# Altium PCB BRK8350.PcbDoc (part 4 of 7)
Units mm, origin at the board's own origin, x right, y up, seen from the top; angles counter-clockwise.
Board outline 240 x 150 mm, 8 copper layers (L1-TOP, L2-GND, L3-PWR, L4-SIG, L5-SIG, L6-PWR, L7-GND, L8-BOT), stack 1.465 mm thick; 277 components, 542 nets, 1814 pads, 2338 vias.
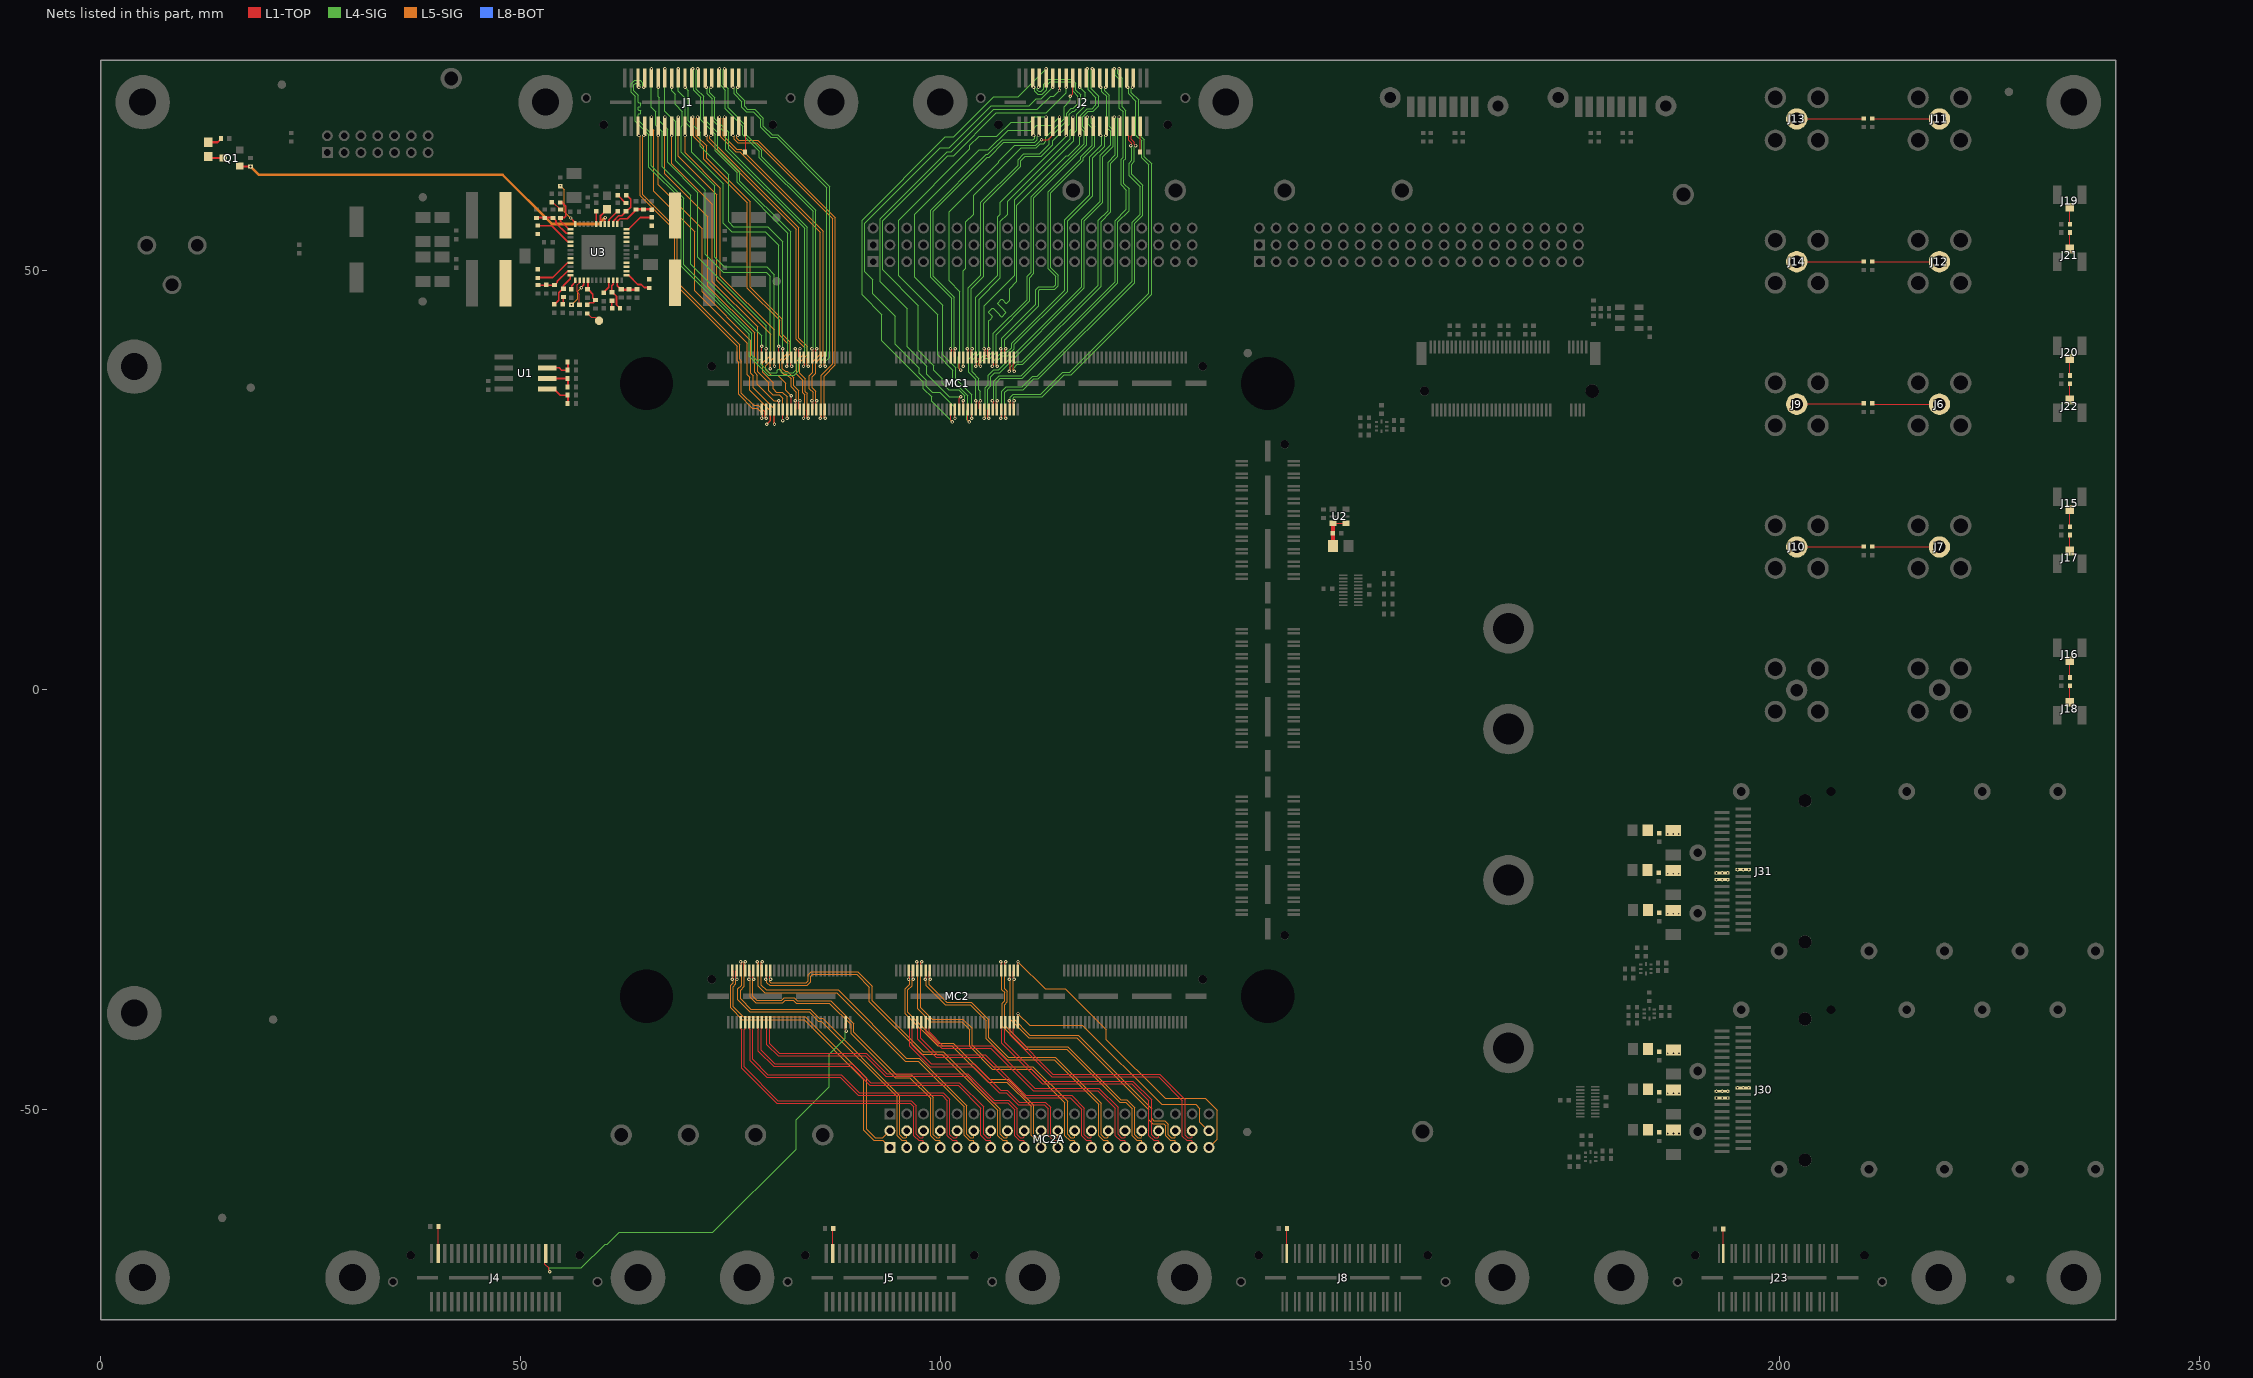
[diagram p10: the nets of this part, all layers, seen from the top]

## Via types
v1: diameter 0.406, hole 0.203, L1-TOP to L8-BOT, tented both sides, 2338 vias

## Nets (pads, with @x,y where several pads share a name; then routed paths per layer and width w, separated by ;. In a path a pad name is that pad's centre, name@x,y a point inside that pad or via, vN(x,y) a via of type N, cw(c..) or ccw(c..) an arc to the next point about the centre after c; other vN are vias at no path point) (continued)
MC2A_1: MC2.3 MC2A.1 | length 34.2
  L1-TOP w0.107: v1(75.212,-34.451) 75.34,-34.323 75.34,-33.5 MC2.3@75.25,-33.41
  L5-SIG w0.107: v1(75.212,-34.451) 75.34,-34.579 75.34,-34.87 75.016,-35.194 75.016,-37.877 76.408,-39.268 83.769,-39.268 90.907,-46.406 90.907,-52.473 92.093,-53.66 93.16,-53.66 MC2A.1@94,-54.5
MC2A_2: MC2.5 MC2A.2 | length 33.6
  L1-TOP w0.107: MC2.5@75.75,-33.41 75.66,-33.5 75.66,-34.323 v1(75.788,-34.451)
  L5-SIG w0.107: v1(75.788,-34.451) 75.66,-34.579 75.66,-35.003 75.336,-35.327 75.336,-37.744 76.54,-38.948 83.902,-38.948 91.227,-46.273 91.227,-52.341 92.226,-53.34 93.16,-53.34 MC2A.2@94,-52.5
MC2A_3: MC2.7 MC2A.3 | length 36.5
  L1-TOP w0.107: v1(76.212,-32.368) 76.34,-32.496 76.34,-33.32 MC2.7@76.25,-33.41
  L5-SIG w0.107: v1(76.212,-32.368) 76.34,-32.496 76.34,-35.166 75.895,-35.611 75.895,-36.928 77.322,-38.354 84.397,-38.354 85.479,-39.436 85.842,-39.436 94.846,-48.44 94.846,-53.085 95.421,-53.66 95.916,-53.66 96,-53.745 MC2A.3@96,-54.5
MC2A_4: MC2.9 MC2A.4 | length 35.9
  L1-TOP w0.107: MC2.9@76.75,-33.41 76.66,-33.32 76.66,-32.496 v1(76.789,-32.368)
  L5-SIG w0.107: v1(76.789,-32.368) 76.66,-32.496 76.66,-35.298 76.215,-35.743 76.215,-36.795 77.454,-38.034 84.529,-38.034 85.611,-39.116 85.974,-39.116 95.166,-48.308 95.166,-52.953 95.553,-53.34 95.916,-53.34 96,-53.255 MC2A.4@96,-52.5
MC2A_5: MC2.8 MC2A.5 | length 33.5
  L1-TOP w0.107: MC2.8@76.25,-39.59 76.25,-40.368 76.34,-40.458 76.34,-45.043 80.537,-49.24 96.419,-49.24 96.842,-49.663 96.842,-53.075 97.427,-53.66 97.922,-53.66 98,-53.738 MC2A.5@98,-54.5
MC2A_6: MC2.10 MC2A.6 | length 33
  L1-TOP w0.107: MC2.10@76.75,-39.59 76.75,-40.368 76.66,-40.458 76.66,-44.91 80.67,-48.92 96.552,-48.92 97.162,-49.531 97.162,-52.942 97.56,-53.34 97.922,-53.34 98,-53.262 MC2A.6@98,-52.5
MC2A_7: MC2.11 MC2A.7 | length 37.3
  L1-TOP w0.107: v1(77.212,-34.451) 77.34,-34.323 77.34,-33.5 MC2.11@77.25,-33.41
  L5-SIG w0.107: v1(77.212,-34.451) 77.34,-34.579 77.34,-36.62 78.008,-37.287 81.225,-37.287 81.555,-36.957 82.474,-36.957 82.834,-37.318 86.797,-37.318 89.383,-39.903 89.383,-40.933 94.616,-46.167 96.381,-46.167 98.847,-48.632 98.847,-53.085 99.421,-53.66 99.903,-53.66 100,-53.757 MC2A.7@100,-54.5
MC2A_8: MC2.13 MC2A.8 | length 36.8
  L1-TOP w0.107: MC2.13@77.75,-33.41 77.66,-33.5 77.66,-34.323 v1(77.788,-34.451)
  L5-SIG w0.107: v1(77.788,-34.451) 77.66,-34.579 77.66,-36.487 78.141,-36.967 81.092,-36.967 81.422,-36.637 82.606,-36.637 82.967,-36.998 86.929,-36.998 89.703,-39.771 89.703,-40.801 94.749,-45.847 96.514,-45.847 99.167,-48.5 99.167,-52.953 99.554,-53.34 99.903,-53.34 100,-53.243 MC2A.8@100,-52.5
MC2A_9: MC2.12 MC2A.9 | length 36.4
  L1-TOP w0.107: MC2.12@77.25,-39.59 77.25,-40.368 77.34,-40.458 77.34,-44.142 79.34,-46.142 88.067,-46.142 90.2,-48.275 100.204,-48.275 100.836,-48.907 100.836,-53.085 101.411,-53.66 101.897,-53.66 102,-53.763 MC2A.9@102,-54.5
MC2A_10: MC2.14 MC2A.10 | length 35.9
  L1-TOP w0.107: MC2.14@77.75,-39.59 77.75,-40.368 77.66,-40.458 77.66,-44.009 79.473,-45.822 88.199,-45.822 90.333,-47.955 100.337,-47.955 101.156,-48.774 101.156,-52.952 101.544,-53.34 101.897,-53.34 102,-53.237 MC2A.10@102,-52.5
MC2A_11: MC2.15 MC2A.11 | length 40.1
  L1-TOP w0.107: v1(78.212,-32.368) 78.34,-32.496 78.34,-33.32 MC2.15@78.25,-33.41
  L5-SIG w0.107: v1(78.212,-32.368) 78.34,-32.496 78.34,-35.283 79.115,-36.058 87.694,-36.058 95.839,-44.202 97.382,-44.202 102.834,-49.655 102.834,-53.035 103.46,-53.66 103.917,-53.66 104,-53.744 MC2A.11@104,-54.5
MC2A_12: MC2.17 MC2A.12 | length 39.6
  L1-TOP w0.107: MC2.17@78.75,-33.41 78.66,-33.32 78.66,-32.496 v1(78.788,-32.368)
  L5-SIG w0.107: v1(78.788,-32.368) 78.66,-32.496 78.66,-35.15 79.248,-35.738 87.827,-35.738 95.971,-43.882 97.515,-43.882 103.155,-49.522 103.155,-52.902 103.592,-53.34 103.917,-53.34 104,-53.256 MC2A.12@104,-52.5
MC2A_13: MC2.16 MC2A.13 | length 38.2
  L1-TOP w0.107: MC2.16@78.25,-39.59 78.25,-40.368 78.34,-40.458 78.34,-43.03 80.157,-44.846 89.377,-44.846 91.612,-47.081 102.128,-47.081 104.841,-49.795 104.841,-53.059 105.443,-53.66 105.91,-53.66 106,-53.75 MC2A.13@106,-54.5
MC2A_14: MC2.18 MC2A.14 | length 37.7
  L1-TOP w0.107: MC2.18@78.75,-39.59 78.75,-40.368 78.66,-40.458 78.66,-42.897 80.289,-44.526 89.51,-44.526 91.745,-46.761 102.26,-46.761 105.161,-49.662 105.161,-52.926 105.575,-53.34 105.91,-53.34 106,-53.25 MC2A.14@106,-52.5
MC2A_15: MC2.19 MC2A.15 | length 43.1
  L1-TOP w0.107: v1(79.212,-34.451) 79.34,-34.323 79.34,-33.5 MC2.19@79.25,-33.41
  L5-SIG w0.107: v1(79.212,-34.451) 79.34,-34.579 79.34,-34.865 79.68,-35.204 84.146,-35.204 84.597,-34.753 84.597,-34.08 84.793,-33.884 90.043,-33.884 91.567,-35.408 91.567,-37.13 97.854,-43.418 100.191,-43.418 106.835,-50.061 106.835,-53.073 107.422,-53.66 107.917,-53.66 108,-53.743 MC2A.15@108,-54.5
MC2A_16: MC2.21 MC2A.16 | length 42.6
  L1-TOP w0.107: MC2.21@79.75,-33.41 79.66,-33.5 79.66,-34.323 v1(79.788,-34.451)
  L5-SIG w0.107: v1(79.788,-34.451) 79.66,-34.579 79.66,-34.732 79.812,-34.884 84.013,-34.884 84.277,-34.62 84.277,-33.947 84.661,-33.564 90.176,-33.564 91.887,-35.275 91.887,-36.998 97.987,-43.098 100.324,-43.098 107.155,-49.929 107.155,-52.94 107.555,-53.34 107.917,-53.34 108,-53.257 MC2A.16@108,-52.5
MC2A_17: MC2.20 MC2A.17 | length 40.7
  L1-TOP w0.107: MC2.20@79.25,-39.59 79.25,-40.368 79.34,-40.458 79.34,-42.252 80.68,-43.591 91.054,-43.591 93.478,-46.015 103.144,-46.015 106.319,-49.19 108.031,-49.19 108.842,-50 108.842,-53.097 109.405,-53.66 109.898,-53.66 110,-53.762 MC2A.17@110,-54.5
MC2A_18: MC2.22 MC2A.18 | length 40.1
  L1-TOP w0.107: MC2.22@79.75,-39.59 79.75,-40.368 79.66,-40.458 79.66,-42.119 80.812,-43.271 91.187,-43.271 93.61,-45.695 103.276,-45.695 106.451,-48.87 108.164,-48.87 109.162,-49.868 109.162,-52.964 109.537,-53.34 109.898,-53.34 110,-53.238 MC2A.18@110,-52.5
MC2A_19: MC2.67 MC2A.19 | length 30.7
  L1-TOP w0.107: v1(96.212,-34.451) 96.34,-34.323 96.34,-33.5 MC2.67@96.25,-33.41
  L5-SIG w0.107: v1(96.212,-34.451) 96.34,-34.579 96.34,-35.077 95.834,-35.584 95.834,-38.548 99.686,-42.399 101.382,-42.399 105.7,-46.717 107.942,-46.717 110.835,-49.61 110.835,-53.068 111.427,-53.66 111.892,-53.66 112,-53.768 MC2A.19@112,-54.5
MC2A_20: MC2.69 MC2A.20 | length 30.2
  L1-TOP w0.107: MC2.69@96.75,-33.41 96.66,-33.5 96.66,-34.323 v1(96.788,-34.451)
  L5-SIG w0.107: v1(96.788,-34.451) 96.66,-34.579 96.66,-35.21 96.154,-35.716 96.154,-38.415 99.818,-42.079 101.515,-42.079 105.833,-46.397 108.075,-46.397 111.156,-49.478 111.156,-52.936 111.56,-53.34 111.892,-53.34 112,-53.232 MC2A.20@112,-52.5
MC2A_21: MC2.68 MC2A.21 | length 27.8
  L1-TOP w0.107: MC2.68@96.25,-39.59 96.25,-40.094 96.34,-40.184 96.34,-42.436 98.776,-44.872 103.901,-44.872 107.016,-47.986 107.853,-47.986 109.278,-49.412 112.39,-49.412 112.842,-49.864 112.842,-53.028 113.474,-53.66 113.911,-53.66 114,-53.749 MC2A.21@114,-54.5
MC2A_22: MC2.70 MC2A.22 | length 27.3
  L1-TOP w0.107: MC2.70@96.75,-39.59 96.75,-39.973 96.66,-40.063 96.66,-42.304 98.908,-44.552 104.059,-44.552 107.174,-47.666 107.985,-47.666 109.411,-49.092 112.523,-49.092 113.162,-49.732 113.162,-52.895 113.607,-53.34 113.911,-53.34 114,-53.251 MC2A.22@114,-52.5
MC2A_23: MC2.71 MC2A.23 | length 36.2
  L1-TOP w0.107: v1(97.212,-32.368) 97.34,-32.496 97.34,-33.32 MC2.71@97.25,-33.41
  L5-SIG w0.107: v1(97.212,-32.368) 97.34,-32.496 97.34,-37.976 98.887,-39.522 102.565,-39.522 103.49,-40.447 103.49,-42.463 106.201,-45.174 110.87,-45.174 114.836,-49.14 114.836,-53.073 115.423,-53.66 115.918,-53.66 116,-53.742 MC2A.23@116,-54.5
MC2A_24: MC2.73 MC2A.24 | length 35.7
  L1-TOP w0.107: MC2.73@97.75,-33.41 97.66,-33.32 97.66,-32.496 v1(97.788,-32.368)
  L5-SIG w0.107: v1(97.788,-32.368) 97.66,-32.496 97.66,-37.843 99.019,-39.202 102.698,-39.202 103.81,-40.314 103.81,-42.33 106.333,-44.854 111.002,-44.854 115.156,-49.008 115.156,-52.94 115.556,-53.34 115.918,-53.34 116,-53.258 MC2A.24@116,-52.5
MC2A_25: MC2.72 MC2A.25 | length 30.3
  L1-TOP w0.107: MC2.72@97.25,-39.59 97.25,-40.159 97.34,-40.249 97.34,-41.602 98.877,-43.138 99.492,-43.754 105.197,-43.754 110.042,-48.599 115.502,-48.599 116.843,-49.94 116.843,-53.089 117.414,-53.66 117.925,-53.66 118,-53.735 MC2A.25@118,-54.5
MC2A_26: MC2.74 MC2A.26 | length 29.8
  L1-TOP w0.107: MC2.74@97.75,-39.59 97.75,-40.132 97.66,-40.222 97.66,-41.469 99.625,-43.434 105.329,-43.434 110.174,-48.279 115.635,-48.279 117.163,-49.807 117.163,-52.956 117.546,-53.34 117.925,-53.34 118,-53.265 MC2A.26@118,-52.5
MC2A_27: MC2.75 MC2A.27 | length 35.5
  L1-TOP w0.107: v1(98.212,-34.451) 98.34,-34.323 98.34,-33.5 MC2.75@98.25,-33.41
  L5-SIG w0.107: v1(98.212,-34.451) 98.34,-34.579 98.34,-35.242 100.608,-37.51 103.546,-37.51 105.461,-39.425 105.461,-41.568 107.961,-44.069 113.568,-44.069 118.849,-49.35 118.849,-53.085 119.424,-53.66 119.906,-53.66 120,-53.754 MC2A.27@120,-54.5
MC2A_28: MC2.77 MC2A.28 | length 35
  L1-TOP w0.107: MC2.77@98.75,-33.41 98.66,-33.5 98.66,-34.323 v1(98.788,-34.451)
  L5-SIG w0.107: v1(98.788,-34.451) 98.66,-34.579 98.66,-35.11 100.74,-37.19 103.678,-37.19 105.781,-39.292 105.781,-41.436 108.094,-43.749 113.701,-43.749 119.169,-49.218 119.169,-52.953 119.556,-53.34 119.906,-53.34 120,-53.246 MC2A.28@120,-52.5
MC2A_29: MC2.76 MC2A.29 | length 32.9
  L1-TOP w0.107: MC2.76@98.25,-39.59 98.25,-40.059 98.34,-40.149 98.34,-40.856 100.172,-42.687 106.035,-42.687 111.093,-47.746 118.75,-47.746 120.846,-49.841 120.846,-53.075 121.43,-53.66 121.912,-53.66 122,-53.748 MC2A.29@122,-54.5
MC2A_30: MC2.78 MC2A.30 | length 32.4
  L1-TOP w0.107: MC2.78@98.75,-39.59 98.75,-39.982 98.66,-40.072 98.66,-40.723 100.305,-42.367 106.167,-42.367 111.226,-47.426 118.883,-47.426 121.166,-49.709 121.166,-52.943 121.563,-53.34 121.912,-53.34 122,-53.252 MC2A.30@122,-52.5
MC2A_31: MC2.111 MC2A.31 | length 34.1
  L1-TOP w0.107: v1(107.212,-32.368) 107.34,-32.496 107.34,-33.32 MC2.111@107.25,-33.41
  L5-SIG w0.107: v1(107.212,-32.368) 107.34,-32.496 107.34,-35.708 107.671,-36.038 107.671,-37.02 107.353,-37.338 107.353,-40.064 110.114,-42.824 115.062,-42.824 121.351,-49.113 122.067,-49.113 122.84,-49.886 122.84,-53.101 123.399,-53.66 123.906,-53.66 124,-53.754 MC2A.31@124,-54.5
MC2A_32: MC2.113 MC2A.32 | length 33.6
  L1-TOP w0.107: MC2.113@107.75,-33.41 107.66,-33.32 107.66,-32.496 v1(107.788,-32.368)
  L5-SIG w0.107: v1(107.788,-32.368) 107.66,-32.496 107.66,-35.575 107.991,-35.905 107.991,-37.153 107.673,-37.471 107.673,-39.931 110.246,-42.504 115.195,-42.504 121.484,-48.793 122.2,-48.793 123.16,-49.753 123.16,-52.968 123.531,-53.34 123.906,-53.34 124,-53.246 MC2A.32@124,-52.5
MC2A_33: MC2.112 MC2A.33 | length 29.2
  L1-TOP w0.107: MC2.112@107.25,-39.59 107.25,-40.368 107.34,-40.458 107.34,-42.088 112.16,-46.908 122.809,-46.908 124.844,-48.943 124.844,-53.085 125.418,-53.66 125.9,-53.66 126,-53.76 MC2A.33@126,-54.5
MC2A_34: MC2.114 MC2A.34 | length 28.7
  L1-TOP w0.107: MC2.114@107.75,-39.59 107.75,-40.368 107.66,-40.458 107.66,-41.955 112.293,-46.588 122.941,-46.588 125.164,-48.81 125.164,-52.953 125.551,-53.34 125.9,-53.34 126,-53.24 MC2A.34@126,-52.5
MC2A_35: MC2.115 MC2A.35 | length 33.8
  L1-TOP w0.107: v1(108.212,-34.451) 108.34,-34.323 108.34,-33.5 MC2.115@108.25,-33.41
  L5-SIG w0.107: v1(108.212,-34.451) 108.34,-34.579 108.34,-39.222 110.545,-41.427 116.281,-41.427 124.841,-49.987 124.841,-51.176 125.318,-51.653 126.601,-51.653 126.84,-51.892 126.84,-53.113 127.387,-53.66 127.932,-53.66 128,-53.728 MC2A.35@128,-54.5
MC2A_36: MC2.117 MC2A.36 | length 33.3
  L1-TOP w0.107: MC2.117@108.75,-33.41 108.66,-33.5 108.66,-34.323 v1(108.788,-34.451)
  L5-SIG w0.107: v1(108.788,-34.451) 108.66,-34.579 108.66,-39.09 110.678,-41.107 116.414,-41.107 125.161,-49.855 125.161,-51.044 125.451,-51.333 126.734,-51.333 127.16,-51.76 127.16,-52.981 127.519,-53.34 127.932,-53.34 128,-53.272 MC2A.36@128,-52.5
MC2A_37: MC2.116 MC2A.37 | length 31.7
  L1-TOP w0.107: MC2.116@108.25,-39.59 108.25,-40.368 108.34,-40.458 108.34,-41.157 113.278,-46.095 126.015,-46.095 128.847,-48.927 128.847,-53.164 129.343,-53.66 129.913,-53.66 130,-53.747 MC2A.37@130,-54.5
MC2A_38: MC2.118 MC2A.38 | length 31.2
  L1-TOP w0.107: MC2.118@108.75,-39.59 108.75,-40.368 108.66,-40.458 108.66,-41.025 113.41,-45.775 126.147,-45.775 129.167,-48.794 129.167,-53.032 129.475,-53.34 129.913,-53.34 130,-53.253 MC2A.38@130,-52.5
MC2A_39: MC2.119 MC2A.39 | length 37.6
  L1-TOP w0.114: MC2.119@109.25,-33.41 v1(109.25,-32.37)
  L5-SIG w0.117: v1(109.25,-32.37) 112.494,-35.614 114.912,-35.614 119.786,-40.488 119.786,-41.656 126.771,-48.641 131.547,-48.641 132.994,-50.089 132.994,-53.506 MC2A.39@132,-54.5
MC2A_40: MC2.120 MC2A.40 | length 30.5
  L1-TOP w0.114: MC2.120@109.25,-39.59 v1(109.25,-38.55)
  L5-SIG w0.117: v1(109.25,-38.55) 110.629,-39.929 116.916,-39.929 126.365,-49.378 130.404,-49.378 130.912,-49.886 130.912,-51.511 MC2A.40@131.953,-52.553
NetC4_2: C4.2 FB7.2 U2.1 U2.6 | length 4.2
  L1-TOP w0.127: U2.6@146.779,19.844 U2.1@148.329,19.844
  L1-TOP w0.508: U2.6@146.779,19.844 146.779,17.166 FB7.2@146.793,17.151
NetC6_1: C6.1 J6.1 | length 8
  L1-TOP w0.107: C6.1@210.99,34.07 ccw(c211.097,34.177) 211.097,34.026 J6.1@219,34.026
NetC7_1: C7.1 J7.1 | length 8
  L1-TOP w0.107: C7.1@210.99,17.027 J7.1@219,17.026
NetC8_1: C8.1 J9.1 | length 8
  L1-TOP w0.107: J9.1@202,34.026 cw(c202.107,33.919) 202.107,34.07 C8.1@210,34.07
NetC9_1: C9.1 J10.1 | length 8
  L1-TOP w0.107: J10.1@202,17.026 C9.1@209.999,17.026
NetC10_1: C10.1 J11.1 | length 7.9
  L1-TOP w0.107: C10.1@211.102,68.005 211.108,68.005 211.113,68 J11.1@219,68
NetC11_1: C11.1 J12.1 | length 8
  L1-TOP w0.107: C11.1@210.99,50.977 218.945,50.977 ccw(c218.945,51.055) J12.1@219,51
NetC12_1: C12.1 J13.1 | length 7.9
  L1-TOP w0.107: J13.1@202,68 209.887,68 209.892,68.005 C12.1@209.898,68.005
NetC13_1: C13.1 J14.1 | length 8
  L1-TOP w0.107: J14.1@202,51 209.945,51 cw(c209.945,50.923) C13.1@210,50.977
NetC14_1: C14.1 J15.1 | length 2
  L1-TOP w0.107: C14.1@234.493,19.449 234.5,19.456 J15.1@234.5,21.475
NetC15_1: C15.1 J16.1 | length 2
  L1-TOP w0.107: C15.1@234.493,1.475 234.5,1.481 J16.1@234.5,3.475
NetC16_1: C16.1 J17.1 | length 1.9
  L1-TOP w0.107: C16.1@234.493,18.449 234.5,18.443 J17.1@234.5,16.525
NetC17_1: C17.1 J18.1 | length 2
  L1-TOP w0.107: C17.1@234.493,0.475 234.5,0.468 J18.1@234.5,-1.475
NetC18_1: C18.1 J19.1 | length 2
  L1-TOP w0.107: C18.1@234.493,55.475 234.5,55.481 J19.1@234.5,57.475
NetC19_1: C19.1 J20.1 | length 2
  L1-TOP w0.107: C19.1@234.493,37.449 234.5,37.456 J20.1@234.5,39.475
NetC20_1: C20.1 J21.1 | length 2
  L1-TOP w0.107: C20.1@234.493,54.475 234.5,54.468 J21.1@234.5,52.525
NetC21_1: C21.1 J22.1 | length 1.9
  L1-TOP w0.107: C21.1@234.493,36.449 234.5,36.443 J22.1@234.5,34.525
NetC30_2: C30.2 U3.18 | length 2.1
  L1-TOP w0.203: U3.18@59.542,55.49 59.542,56.492 C30.2@60.308,57.258
NetC31_2: C31.2 U3.19 | length 1.6
  L1-TOP w0.203: C31.2@59.038,57.064 59.038,55.494 U3.19@59.042,55.49
NetC35_1: C35.1 U3.1 | length 3.3
  L1-TOP w0.203: U3.1@62.642,49.39 62.876,49.39 63.984,48.281 64.391,48.281 64.749,47.922 C35.1@65.331,47.922
NetC35_2: C35.2 L1.1 U3.2 U3.3 U3.4
NetC41_1: C41.1 R16.1 R17.2 U3.47 | length 3.2
  L1-TOP w0.152: U3.47@61.542,48.79 61.542,48.132 R17.2@62.003,47.671
  L1-TOP w0.305: R17.2@62.003,47.671 62.013,47.681 C41.1@63.883,47.681
NetC42_1: C42.1 R18.2 | length 1
  L1-TOP w0.152: C42.1@60.87,45.459 60.893,45.482 R18.2@60.893,46.406
NetC43_1: C43.1 U3.45 | length 1.8
  L1-TOP w0.152: C43.1@59.93,47.266 59.93,47.353 60.542,47.965 U3.45@60.542,48.79
NetC44_1: C44.1 R18.1 U3.46 | length 3.9
  L1-TOP w0.152: R18.1@60.886,47.422 60.886,48.128 61.042,48.285 U3.46@61.042,48.79
  L1-TOP w0.203: R18.1@60.886,47.422 61.444,46.864 61.444,45.871 C44.1@61.902,45.413
NetC45_1: C45.1 U3.12 | length 3.6
  L1-TOP w0.203: U3.12@62.642,54.89 62.906,54.89 64.274,56.257 C45.1@65.642,56.257
NetC45_2: C45.2 L2.1 U3.9 U3.10 U3.11
NetC51_2: C51.2 U3.16 | length 2
  L1-TOP w0.203: U3.16@60.542,55.49 60.542,56.003 C51.2@61.578,57.039
NetC52_1: C52.1 R19.1 R20.2 U3.14 | length 5.1
  L1-TOP w0.203: U3.14@61.542,55.49 61.542,55.813 61.857,56.127 62.705,56.127 63.773,57.195 R20.2@63.773,57.242
  L1-TOP w0.305: R20.2@63.763,57.252 65.632,57.252 C52.1@65.642,57.242
NetC53_1: C53.1 R21.2 | length 1.4
  L1-TOP w0.203: C53.1@61.592,58.944 62.557,57.979 R21.2@62.557,57.949
NetC54_1: C54.1 R21.1 U3.15 | length 4.7
  L1-TOP w0.178: R21.1@62.557,57.049 62.666,57.049 63.116,57.499 63.116,58.423 C54.1@62.594,58.944
  L1-TOP w0.203: U3.15@61.042,55.49 61.042,55.82 61.68,56.458 62.081,56.458 R21.1@62.557,56.934
NetC55_1: C55.1 U3.24 | length 5.3
  L1-TOP w0.203: v1(55.99,56.204) 56.542,55.652 U3.24@56.542,55.49
  L5-SIG w0.127: v1(54.729,60.051) 55.237,59.543 55.237,56.957 v1(55.99,56.204)
NetC56_1: C56.1 U3.28 | length 4.7
  L1-TOP w0.203: C56.1@52.053,55.267 53.742,55.267 55.619,53.39 U3.28@55.942,53.39
NetC56_2: C56.2 L3.1 U3.29
NetC62_1: C62.1 R22.1 R24.2 U3.26 | length 5
  L1-TOP w0.203: R22.1@51.926,56.262 53.857,56.262 54.238,55.881 54.238,55.59 55.439,54.39 U3.26@55.942,54.39
NetC63_1: C63.1 U3.37 | length 1.3
  L1-TOP w0.203: C63.1@56.092,47.669 56.092,48.126 56.542,48.577 U3.37@56.542,48.79
NetC64_1: C64.1 R23.2 | length 1.4
  L1-TOP w0.127: C64.1@53.73,58.131 53.802,58.131 R23.2@54.771,57.162
NetC65_1: C65.1 R23.1 U3.25 | length 4.5
  L1-TOP w0.203: C65.1@54.974,58.106 54.974,58.02 55.394,57.6 55.394,56.407 55.249,56.262 54.771,56.262 54.771,55.848 55.73,54.89 U3.25@55.942,54.89
NetC66_1: C66.1 U3.33 | length 4.6
  L1-TOP w0.203: C66.1@52.053,49.114 53.829,49.114 55.604,50.89 U3.33@55.942,50.89
NetC66_2: C66.2 L4.1 U3.32
NetC70_1: C70.1 R26.1 R29.2 U3.35 | length 4.6
  L1-TOP w0.203: R26.1@52.104,48.177 52.114,48.187 53.069,48.187 54.017,48.187 54.035,48.17 54.388,48.523 54.388,48.661 55.616,49.89 U3.35@55.942,49.89
NetC71_1: C71.1 TP21.1 | length 1.8
  L1-TOP w0.127: C71.1@57.972,44.885 58.451,44.405 58.92,44.405 TP21.1@59.352,43.974
NetC71_2: C71.2 C73.2 R28.2 U3.40 | length 4.1
  L1-TOP w0.178: C71.2@57.972,45.805 58.274,46.107 58.655,46.107 58.937,46.389 58.632,46.694 58.632,47.137 58.105,47.664 R28.2@57.99,47.664
  L1-TOP w0.203: R28.2@57.99,47.664 58.042,47.716 U3.40@58.042,48.79
NetC72_1: C72.1 R27.2 | length 1
  L1-TOP w0.203: C72.1@55.051,45.894 C72.1@55.101,45.945 ; C72.1@55.101,45.894 C72.1@55.101,45.945 ; R27.2@55.101,46.838 C72.1@55.101,45.945
NetC74_1: C74.1 R27.1 U3.36 | length 4.3
  L1-TOP w0.203: C74.1@54.035,45.891 54.568,46.425 54.568,47.288 55.101,47.822 55.101,48.114 55.942,48.955 U3.36@55.942,49.39
NetC90_2: C90.2 C91.2 FB1.2 J30.29
  other v1: 192.448,-47.8 193.12,-47.8 193.793,-47.8 186.657,-43.271 187.317,-43.271 187.978,-43.271
NetC92_2: C92.2 C93.2 FB2.2 J30.10
  other v1: 186.657,-52.83 187.317,-52.83 187.978,-52.83 194.958,-47.4 195.63,-47.4 196.303,-47.4
NetC94_2: C94.2 C95.2 FB3.1 J30.30
  other v1: 192.448,-48.6 193.12,-48.6 193.793,-48.6 186.657,-48.046 187.317,-48.046 187.978,-48.046
NetC102_2: C102.2 C103.2 FB4.2 J31.29
  other v1: 192.448,-21.8 193.12,-21.8 193.792,-21.8 186.632,-17.16 187.292,-17.16 187.952,-17.16
NetC104_2: C104.2 C105.2 FB5.2 J31.10
  other v1: 186.632,-26.664 187.292,-26.664 187.952,-26.664 194.958,-21.4 195.63,-21.4 196.302,-21.4
NetC106_2: C106.2 C107.2 FB6.1 J31.30
  other v1: 192.448,-22.6 193.12,-22.6 193.792,-22.6 186.632,-21.91 187.292,-21.91 187.952,-21.91
NetD1_1: D1.1 Q1.3 | length 1.9
  L1-TOP w0.254: D1.1@12.795,63.52 12.968,63.347 Q1.3@14.586,63.347
NetD1_2: D1.2 R30.1 | length 1.8
  L1-TOP w0.254: D1.2@12.795,65.22 13.932,65.22 R30.1@14.377,65.665
NetJ1_4: J1.4 R1.2 | length 3.1
  L1-TOP w0.127: J1.4@76.801,67.135 76.803,64.046 R1.2@76.809,64.04
NetJ2_4: J2.4 R2.2 | length 3.1
  L1-TOP w0.127: J2.4@123.803,67.135 123.803,64.062 R2.2@123.825,64.04
NetJ4_4: J4.4 R9.2 | length 3.2
  L1-TOP w0.127: R9.2@40.193,-63.926 40.198,-63.93 J4.4@40.199,-67.135
NetJ5_4: J5.4 R10.2 | length 3
  L1-TOP w0.127: J5.4@87.199,-67.135 87.198,-64.158 R10.2@87.202,-64.154
NetJ8_4: J8.4 R12.2 | length 3
  L1-TOP w0.127: J8.4@141.25,-67.13 141.25,-64.164 R12.2@141.26,-64.154
NetJ23_4: J23.4 R13.2 | length 2.9
  L1-TOP w0.127: R13.2@193.2,-64.23 193.25,-64.28 J23.4@193.25,-67.13
NetQ1_1: Q1.1 R31.1 U3.17 | length 47.5
  L1-TOP w0.178: U3.17@60.042,55.49 60.042,56.211 v1(60.089,56.257)
  L1-TOP w0.254: Q1.1@16.586,62.397 16.637,62.346 v1(17.85,62.346)
  L5-SIG w0.305: v1(17.85,62.346) 18.854,61.341 47.89,61.341 53.739,55.493 59.324,55.493 v1(60.089,56.257)
NetR3_1: R3.1 R6.2 U1.1 | length 3.8
  L1-TOP w0.203: U1.1@53.189,35.82 54.043,35.82 54.754,35.109 55.669,35.109 R3.1@55.669,34.118
NetR4_1: R4.1 R7.2 U1.2 | length 3.5
  L1-TOP w0.203: U1.2@53.189,37.09 55.669,37.09 R4.1@55.669,36.1
NetR5_1: R5.1 R8.2 U1.3 | length 3.6
  L1-TOP w0.203: U1.3@53.189,38.36 54.602,38.36 54.881,38.081 55.669,38.081 R8.2@55.669,39.071
NetR14_1: R14.1 U3.39 | length 3.6
  L1-TOP w0.203: v1(57.26,47.898) 57.26,47.974 57.542,48.256 U3.39@57.542,48.79
  L5-SIG w0.127: v1(56.067,45.871) 56.117,45.871 56.838,46.592 56.838,47.475 v1(57.26,47.898)
  L8-BOT w0.127: v1(57.26,47.898) v1@57.279,47.916
NetR25_2: R25.2 U3.38 | length 3.2
  L1-TOP w0.127: R25.2@57.027,45.821 57.027,47.129 56.736,47.42 56.736,48.215 56.77,48.249 56.771,48.249 57.042,48.52 U3.38@57.042,48.79
PORTA_C2P_CLKN: J1.36 MC1.18 | length 41.3
  L1-TOP w0.107: v1(78.712,32.369) 78.84,32.497 78.84,33.32 MC1.18@78.75,33.41
  L5-SIG w0.107: v1(64.108,66.034) 64.241,65.901 64.241,58.852 68.347,54.746 68.347,48.396 75.794,40.949 75.794,39.232 75.997,39.028 75.997,35.184 77.627,33.553 78.207,33.553 78.84,32.92 78.84,32.497 v1(78.712,32.369)
PORTA_C2P_CLKP: J1.34 MC1.20 | length 41.3
  L1-TOP w0.107: MC1.20@79.25,33.41 79.16,33.32 79.16,32.497 v1(79.289,32.369)
  L5-SIG w0.107: v1(64.694,66.034) 64.561,65.901 64.561,58.985 68.667,54.879 68.667,48.529 76.114,41.082 76.114,39.364 76.317,39.161 76.317,35.316 77.76,33.873 78.339,33.873 79.16,33.052 79.16,32.497 v1(79.289,32.369)
PORTA_P2C_CLKN: J1.35 MC1.33 | length 51.4
  L1-TOP w0.107: v1(82.712,40.632) 82.84,40.504 82.84,39.68 MC1.33@82.75,39.59
  L4-SIG w0.107: v1(64.108,71.764) 64.241,71.897 64.241,72.148 64.109,72.279 63.714,72.279 63.505,72.071 63.505,71.339 63.998,70.846 63.998,70.256 63.998,69.998 64.085,69.911 64.236,69.911 64.323,69.824 64.323,69.561 64.236,69.474 64.085,69.474 63.998,69.387 63.998,69.125 64.085,69.037 64.236,69.037 64.323,68.95 64.323,68.688 64.236,68.6 64.085,68.6 63.998,68.513 63.998,68.163 63.998,67.945 63.998,67.839 65.59,66.247 65.59,62.399 69.449,58.541 69.449,50.617 77.572,42.494 77.572,39.853 78.194,39.23 78.236,39.188 78.36,39.188 78.526,39.354 78.649,39.354 78.834,39.169 78.834,39.045 78.669,38.879 78.669,38.756 78.916,38.508 79.07,38.354 79.654,37.77 80.391,37.77 80.522,37.77 80.609,37.857 80.609,38.092 80.697,38.179 80.959,38.179 81.046,38.092 81.046,37.857 81.134,37.77 81.28,37.77 82.474,37.77 82.84,38.136 82.84,40.504 v1(82.712,40.632)
PORTA_P2C_CLKP: J1.33 MC1.35 | length 51.4
  L1-TOP w0.107: MC1.35@83.25,39.59 83.16,39.68 83.16,40.504 v1(83.288,40.632)
  L4-SIG w0.107: v1(64.694,71.764) 64.561,71.897 64.561,72.28 64.242,72.599 63.581,72.599 63.185,72.203 63.185,71.206 63.678,70.714 63.678,67.707 65.27,66.114 65.27,62.266 69.129,58.408 69.129,50.485 77.252,42.362 77.252,39.72 79.522,37.45 82.606,37.45 83.16,38.004 83.16,40.504 v1(83.288,40.632)
PORTA_S0_D0P: J1.5 MC1.47 | length 40.2
  L1-TOP w0.107: MC1.47@86.25,39.59 86.16,39.5 86.16,38.677 v1(86.288,38.549)
  L4-SIG w0.107: v1(75.895,71.764) 75.762,71.631 75.762,71.114 76.688,70.189 76.688,69.5 77.024,69.164 77.882,69.164 78.933,68.113 78.933,67.142 79.961,66.114 80.637,66.114 86.807,59.944 86.807,39.644 86.16,38.997 86.16,38.677 v1(86.288,38.549)
PORTA_S1_D1P: J1.6 MC1.48 | length 41.7
  L1-TOP w0.107: MC1.48@86.25,33.41 86.16,33.32 86.16,32.497 v1(86.289,32.369)
  L5-SIG w0.107: v1(75.895,66.034) 75.762,65.901 75.762,65.696 75.987,65.471 78.288,65.471 87.518,56.241 87.518,38.725 86.16,37.367 86.16,32.497 v1(86.289,32.369)
PORTA_S2_D0N: J1.7 MC1.45 | length 40.2
  L1-TOP w0.107: v1(85.712,38.549) 85.84,38.677 85.84,39.5 MC1.45@85.75,39.59
  L4-SIG w0.107: v1(75.309,71.764) 75.442,71.631 75.442,70.982 76.368,70.057 76.368,69.368 76.891,68.844 77.749,68.844 78.613,67.981 78.613,67.01 79.829,65.794 80.504,65.794 86.487,59.811 86.487,39.776 85.84,39.13 85.84,38.677 v1(85.712,38.549)
PORTA_S3_D1N: J1.8 MC1.46 | length 41.7
  L1-TOP w0.107: v1(85.712,32.369) 85.84,32.497 85.84,33.32 MC1.46@85.75,33.41
  L5-SIG w0.107: v1(75.309,66.034) 75.442,65.901 75.442,65.563 75.854,65.151 78.156,65.151 87.198,56.109 87.198,38.857 85.84,37.5 85.84,32.497 v1(85.712,32.369)
PORTA_S4_D2P: J1.9 MC1.43 | length 39.1
  L1-TOP w0.107: MC1.43@85.25,39.59 85.16,39.68 85.16,40.504 v1(85.288,40.632)
  L4-SIG w0.107: v1(74.295,73.966) 74.162,73.833 74.162,72.143 74.724,71.581 74.724,69.333 76.799,67.258 76.799,66.253 78.755,64.298 78.755,63.522 85.16,57.116 85.16,40.76 v1(85.288,40.632)
PORTA_S5_D3P: J1.10 MC1.44 | length 41
  L1-TOP w0.107: MC1.44@85.25,33.41 85.16,33.5 85.16,34.324 v1(85.288,34.452)
  L5-SIG w0.107: v1(74.295,68.236) 74.162,68.103 74.162,66.007 75.761,64.408 76.275,64.408 86.038,54.645 86.038,39.862 85.156,38.98 85.156,37.709 84.734,37.287 84.734,36.003 85.16,35.577 85.16,34.58 v1(85.288,34.452)
PORTA_S6_D2N: J1.11 MC1.41 | length 39.1
  L1-TOP w0.107: v1(84.712,40.632) 84.84,40.504 84.84,39.68 MC1.41@84.75,39.59
  L4-SIG w0.107: v1(73.709,73.966) 73.842,73.833 73.842,72.011 74.404,71.448 74.404,69.2 76.479,67.125 76.479,66.121 78.435,64.165 78.435,63.389 84.84,56.984 84.84,40.76 v1(84.712,40.632)
PORTA_S7_D3N: J1.12 MC1.42 | length 41
  L1-TOP w0.107: v1(84.712,34.452) 84.84,34.324 84.84,33.5 MC1.42@84.75,33.41
  L5-SIG w0.107: v1(73.709,68.236) 73.842,68.103 73.842,65.874 75.629,64.088 76.143,64.088 85.718,54.513 85.718,39.995 84.836,39.113 84.836,37.841 84.414,37.42 84.414,35.871 84.84,35.445 84.84,34.58 v1(84.712,34.452)
PORTA_S8_D4P: J1.13 MC1.39 | length 39.3
  L1-TOP w0.107: MC1.39@84.25,39.59 84.16,39.5 84.16,38.677 v1(84.288,38.549)
  L4-SIG w0.107: v1(72.695,71.764) 72.562,71.631 72.562,71.119 73.162,70.519 73.162,68.051 74.793,66.42 74.793,64.475 84.16,55.108 84.16,38.677 v1(84.288,38.549)
PORTA_S9_D5P: J1.14 MC1.40 | length 40.5
  L1-TOP w0.107: MC1.40@84.25,33.41 84.16,33.32 84.16,32.497 v1(84.289,32.369)
  L5-SIG w0.107: v1(72.695,66.034) 72.562,65.901 72.562,65.625 83.167,55.02 83.167,41.902 84.165,40.904 84.165,39.944 83.236,39.014 83.236,37.738 83.939,37.036 83.939,35.53 84.16,35.308 84.16,32.497 v1(84.289,32.369)
PORTA_S10_D4N: J1.15 MC1.37 | length 39.3
  L1-TOP w0.107: v1(83.712,38.549) 83.84,38.677 83.84,39.5 MC1.37@83.75,39.59
  L4-SIG w0.107: v1(72.109,71.764) 72.242,71.631 72.242,70.987 72.842,70.387 72.842,67.918 74.473,66.288 74.473,64.343 83.84,54.975 83.84,38.677 v1(83.712,38.549)
PORTA_S11_D5N: J1.16 MC1.38 | length 40.5
  L1-TOP w0.107: v1(83.712,32.369) 83.84,32.497 83.84,33.32 MC1.38@83.75,33.41
  L5-SIG w0.107: v1(72.109,66.034) 72.242,65.901 72.242,65.493 82.847,54.887 82.847,41.77 83.845,40.772 83.845,40.077 82.916,39.147 82.916,37.606 83.619,36.903 83.619,35.398 83.84,35.176 83.84,32.497 v1(83.712,32.369)
PORTA_S12_D6P: J1.17 MC1.31 | length 41.3
  L1-TOP w0.107: MC1.31@82.25,39.59 82.16,39.5 82.16,38.677 v1(82.288,38.549)
  L4-SIG w0.107: v1(71.095,73.966) 70.962,73.833 70.962,71.559 71.816,70.705 71.816,68.011 73.497,66.33 73.497,64.344 76.118,61.723 76.118,60.584 82.16,54.541 82.16,38.677 v1(82.288,38.549)
PORTA_S13_D7P: J1.18 MC1.36 | length 41
  L1-TOP w0.107: MC1.36@83.25,33.41 83.16,33.5 83.16,34.324 v1(83.288,34.452)
  L5-SIG w0.107: v1(71.095,68.236) 70.962,68.103 70.962,66.022 72.161,64.822 72.161,63.343 77.358,58.146 77.358,47.965 81.171,44.152 81.171,42.349 82.14,41.38 82.14,40.027 81.204,39.091 81.204,38.242 81.509,37.937 81.794,37.937 82.55,37.181 82.55,36.213 83.16,35.603 83.16,34.58 v1(83.288,34.452)
PORTA_S14_D6N: J1.19 MC1.29 | length 41.3
  L1-TOP w0.107: v1(81.712,38.549) 81.84,38.677 81.84,39.5 MC1.29@81.75,39.59
  L4-SIG w0.107: v1(70.509,73.966) 70.642,73.833 70.642,71.426 71.496,70.572 71.496,67.878 73.177,66.197 73.177,64.211 75.798,61.591 75.798,60.451 81.84,54.408 81.84,38.677 v1(81.712,38.549)
PORTA_S15_D7N: J1.20 MC1.34 | length 41
  L1-TOP w0.107: v1(82.712,34.452) 82.84,34.324 82.84,33.5 MC1.34@82.75,33.41
  L5-SIG w0.107: v1(70.509,68.236) 70.642,68.103 70.642,65.889 71.841,64.689 71.841,63.21 77.038,58.014 77.038,47.833 80.851,44.02 80.851,42.216 81.82,41.248 81.82,40.159 80.884,39.223 80.884,38.11 81.376,37.617 81.661,37.617 82.23,37.048 82.23,36.081 82.84,35.47 82.84,34.58 v1(82.712,34.452)
PORTA_S16: J1.21 MC1.27 | length 39.4
  L1-TOP w0.114: MC1.27@81.25,39.59 v1(81.25,40.632)
  L4-SIG w0.117: v1(69.602,71.764) 69.995,71.371 69.995,67.799 71.399,66.394 71.399,64.745 74.778,61.366 74.778,55.745 75.354,55.169 79.451,55.169 81.25,53.37 v1(81.25,40.632)
PORTA_S17: J1.22 MC1.32 | length 39.2
  L1-TOP w0.114: MC1.32@82.25,33.41 v1(82.25,35.046)
  L5-SIG w0.117: v1(69.602,66.034) 69.602,63.977 73.815,59.764 73.815,49.282 80.212,42.885 80.212,39.649 79.197,38.633 79.197,38.151 79.858,37.49 80.67,37.49 81.61,36.551 81.61,35.686 v1(82.25,35.046)
PORTA_S18: J1.23 MC1.25 | length 41.7
  L1-TOP w0.114: MC1.25@80.75,39.59 v1(80.75,40.926)
  L4-SIG w0.117: v1(68.802,73.966) 68.802,71.279 69.627,70.454 69.627,67.621 70.414,66.834 70.414,64.047 74.168,60.293 74.168,55.55 75.177,54.541 79.165,54.541 80.75,52.955 v1(80.75,40.926)
PORTA_S19: J1.24 MC1.30 | length 43.4
  L1-TOP w0.114: v1(81.75,32.369) MC1.30@81.75,33.41
  L5-SIG w0.117: v1(68.802,68.236) 68.802,63.569 73.381,58.99 73.381,48.768 79.788,42.36 79.788,39.884 78.867,38.962 78.867,37.821 80.112,36.576 80.112,35.839 80.48,35.471 81.166,35.471 81.75,34.886 v1(81.75,32.369)
PORTA_S20: J1.25 MC1.23 | length 42.4
  L1-TOP w0.114: v1(80.25,38.549) MC1.23@80.25,39.59
  L4-SIG w0.117: v1(68.001,71.764) 68.001,71.38 68.42,70.961 68.42,69.755 69.296,68.878 69.296,67.253 69.139,67.095 69.139,64.033 73.152,60.02 73.152,51.504 74.287,50.368 79.324,50.368 80.25,49.442 v1(80.25,38.549)
PORTA_S21: J1.26 MC1.28 | length 41.2
  L1-TOP w0.114: v1(81.25,32.075) MC1.28@81.25,33.41
  L5-SIG w0.117: v1(68.001,66.034) 68.001,62.682 72.868,57.815 72.868,48.608 78.25,43.225 78.25,37.904 79.553,36.601 79.553,35.652 80.051,35.154 80.823,35.154 81.25,34.726 v1(81.25,32.075)
PORTA_S22: J1.27 MC1.21 | length 45.2
  L1-TOP w0.114: v1(79.75,38.255) MC1.21@79.75,39.59
  L4-SIG w0.117: v1(67.201,73.966) 67.201,68.943 68.478,67.666 68.478,63.043 72,59.521 72,51.894 74.135,49.759 79.248,49.759 79.75,49.256 v1(79.75,38.255)
PORTA_S23: J1.28 MC1.26 | length 40.8
  L1-TOP w0.114: MC1.26@80.75,33.41 v1(80.75,34.452)
  L5-SIG w0.117: v1(67.201,68.236) 67.201,61.45 72.314,56.337 72.314,48.082 77.876,42.52 77.876,37.81 78.212,37.475 78.212,36.393 80.153,34.452 v1(80.75,34.452)
PORTA_S24: J1.29 MC1.19 | length 37.5
  L1-TOP w0.114: MC1.19@79.25,39.59 v1(79.25,40.632)
  L4-SIG w0.117: v1(66.401,71.764) 66.401,70.655 66.556,70.5 66.556,67.758 67.513,66.801 67.513,62.84 71.126,59.226 71.126,51.505 79.25,43.381 v1(79.25,40.632)
PORTA_S25: J1.30 MC1.24 | length 41.9
  L1-TOP w0.114: v1(80.25,31.629) MC1.24@80.25,33.41
  L5-SIG w0.117: v1(66.401,66.034) 66.401,60.167 71.628,54.94 71.628,47.422 77.445,41.605 77.445,37.719 77.749,37.414 77.749,35.978 80.25,33.477 v1(80.25,31.629)
PORTA_S26: J1.31 MC1.17 | length 39.8
  L1-TOP w0.114: MC1.17@78.75,39.59 v1(78.75,40.926)
  L4-SIG w0.117: v1(65.601,73.966) 65.601,69.398 66.121,68.878 66.121,67.235 66.904,66.453 66.904,62.306 70.282,58.928 70.282,50.673 78.75,42.204 v1(78.75,40.926)
PORTA_S27: J1.32 MC1.22 | length 44.6
  L1-TOP w0.114: v1(79.324,31.629) 79.75,32.055 MC1.22@79.75,33.41
  L5-SIG w0.117: v1(65.601,68.236) 65.601,66.929 65.888,66.643 65.888,59.391 70.739,54.54 70.739,47.523 77,41.262 77,37.554 77.292,37.262 77.292,35.682 79.788,33.186 79.788,32.093 v1(79.324,31.629)
PORTB_C2P_CLKN: J2.36 MC1.87 | length 35.1
  L1-TOP w0.107: v1(101.212,40.632) 101.34,40.504 101.34,39.68 MC1.87@101.25,39.59
  L4-SIG w0.107: v1(101.212,40.632) 101.34,40.76 101.34,46.64 98.842,49.139 98.842,57.13 105.48,63.768 105.682,63.768 107.443,65.53 111.088,65.53 111.241,65.683 111.241,65.901 v1(111.108,66.034)
PORTB_C2P_CLKP: J2.34 MC1.89 | length 35.1
  L1-TOP w0.107: MC1.89@101.75,39.59 101.66,39.68 101.66,40.504 v1(101.788,40.632)
  L4-SIG w0.107: v1(101.788,40.632) 101.66,40.76 101.66,46.773 99.162,49.271 99.162,56.998 105.612,63.448 105.814,63.448 107.576,65.21 111.221,65.21 111.561,65.55 111.561,65.901 v1(111.694,66.034)
PORTB_P2C_CLKN: J2.35 MC1.95 | length 45.8
  L1-TOP w0.107: v1(103.212,40.632) 103.34,40.504 103.34,39.68 MC1.95@103.25,39.59
  L4-SIG w0.107: v1(103.212,40.632) 103.34,40.76 103.34,47.892 104.839,49.39 104.839,58.085 109.258,62.505 109.258,63.163 109.957,63.862 111.872,63.862 112.992,64.981 112.992,65.71 115.039,67.757 115.039,68.668 115.618,69.247 115.849,69.247 116.393,69.79 116.393,70.732 115.814,71.311 115.814,72.145 115.555,72.403 113.076,72.403 112.657,71.984 112.657,71.489 112.139,70.971 111.585,70.971 111.241,71.316 111.241,71.631 v1(111.108,71.764)
PORTB_P2C_CLKP: J2.33 MC1.97 | length 45.8
  L1-TOP w0.107: MC1.97@103.75,39.59 103.66,39.68 103.66,40.504 v1(103.788,40.632)
  L4-SIG w0.107: v1(103.788,40.632) 103.66,40.76 103.66,47.76 105.159,49.258 105.159,57.953 109.578,62.372 109.578,63.03 110.09,63.542 112.005,63.542 113.373,64.91 113.373,65.385 115.359,67.372 115.359,68.535 115.75,68.927 115.982,68.927 116.713,69.658 116.713,70.865 116.134,71.444 116.134,72.277 115.688,72.723 112.943,72.723 112.337,72.117 112.337,71.622 112.006,71.291 111.718,71.291 111.561,71.448 111.561,71.631 v1(111.694,71.764)
PORTB_S0_D0P: J2.5 MC1.118 | length 48.8
  L1-TOP w0.107: MC1.118@108.75,33.41 108.66,33.5 108.66,34.324 v1(108.789,34.452)
  L4-SIG w0.107: v1(108.789,34.452) 108.66,34.58 108.66,34.751 108.819,34.91 112.121,34.91 114.737,37.526 115.575,37.526 125.161,47.111 125.161,62.667 124.303,63.526 124.303,63.958 124.303,65.51 123.617,66.196 123.617,70.26 122.762,71.114 122.762,71.631 v1(122.895,71.764)
PORTB_S1_D1P: J2.6 MC1.114 | length 45.2
  L1-TOP w0.107: MC1.114@107.75,33.41 107.66,33.32 107.66,32.497 v1(107.788,32.369) ; J2.6@123.002,67.135 123.002,66.206 122.753,65.957 122.753,65.598 123.126,65.226 123.126,64.96 v1(123.259,64.827)
  L4-SIG w0.107: v1(107.788,32.369) 107.66,32.497 107.66,35.423 108.007,35.769 109.887,35.769 111.15,37.033 111.679,37.033 123.165,48.519 123.165,55.55 124.12,56.505 124.12,60.077 122.799,61.397 122.799,62.607 123.126,62.933 123.126,64.694 v1(123.259,64.827)
PORTB_S2_D0N: J2.7 MC1.116 | length 48.8
  L1-TOP w0.107: v1(108.212,34.452) 108.34,34.324 108.34,33.5 MC1.116@108.25,33.41
  L4-SIG w0.107: v1(108.212,34.452) 108.34,34.58 108.34,34.884 108.687,35.23 111.989,35.23 114.605,37.846 115.443,37.846 124.841,47.244 124.841,62.535 123.983,63.393 123.983,64.09 123.983,65.378 123.297,66.063 123.297,70.127 122.442,70.982 122.442,71.631 v1(122.309,71.764)
PORTB_S3_D1N: J2.8 MC1.112 | length 45.2
  L1-TOP w0.107: v1(107.212,32.369) 107.34,32.497 107.34,33.32 MC1.112@107.25,33.41 ; J2.8@122.202,67.135 122.202,66.188 122.433,65.957 122.433,65.466 122.806,65.094 122.806,64.96 v1(122.673,64.827)
  L4-SIG w0.107: v1(107.212,32.369) 107.34,32.497 107.34,35.555 107.874,36.089 109.754,36.089 111.018,37.353 111.547,37.353 122.845,48.651 122.845,55.682 123.8,56.637 123.8,59.944 122.479,61.265 122.479,62.739 122.806,63.066 122.806,64.694 v1(122.673,64.827)
PORTB_S4_D2P: J2.9 MC1.110 | length 49.6
  L1-TOP w0.107: MC1.110@106.75,33.41 106.66,33.5 106.66,34.324 v1(106.789,34.452)
  L4-SIG w0.107: v1(106.789,34.452) 106.66,34.58 106.66,36.607 107.143,37.09 109.755,37.09 121.158,48.493 121.158,55.753 122.494,57.089 122.494,59.67 121.859,60.305 121.859,63.053 122.093,63.286 122.093,68.99 121.658,69.424 121.658,72.86 121.162,73.356 121.162,73.833 v1(121.295,73.966)
PORTB_S5_D3P: J2.10 MC1.117 | length 37.7
  L1-TOP w0.107: MC1.117@108.75,39.59 108.75,38.812 108.66,38.722 108.66,38.078 v1(108.806,37.932)
  L4-SIG w0.107: v1(108.806,37.932) 108.678,38.06 108.678,38.273 109.167,38.763 109.832,38.763 119.151,48.082 119.151,55.778 120.31,56.937 120.31,62.728 121.162,63.58 121.162,68.103 v1(121.295,68.236)
PORTB_S6_D2N: J2.11 MC1.108 | length 49.6
  L1-TOP w0.107: v1(106.212,34.452) 106.34,34.324 106.34,33.5 MC1.108@106.25,33.41
  L4-SIG w0.107: v1(106.212,34.452) 106.34,34.58 106.34,36.74 107.011,37.41 109.622,37.41 120.838,48.626 120.838,55.886 122.174,57.222 122.174,59.538 121.539,60.173 121.539,63.185 121.773,63.419 121.773,68.857 121.338,69.292 121.338,72.727 120.842,73.223 120.842,73.833 v1(120.709,73.966)
PORTB_S7_D3N: J2.12 MC1.115 | length 37.7
  L1-TOP w0.107: v1(108.229,37.932) 108.34,38.043 108.34,38.722 108.25,38.812 MC1.115@108.25,39.59
  L4-SIG w0.107: v1(108.229,37.932) 108.357,38.06 108.357,38.406 109.034,39.083 109.699,39.083 118.831,48.215 118.831,55.911 119.99,57.069 119.99,62.86 120.842,63.713 120.842,68.103 v1(120.709,68.236)
PORTB_S8_D4P: J2.13 MC1.106 | length 47.6
  L1-TOP w0.107: MC1.106@105.75,33.41 105.66,33.32 105.66,32.497 v1(105.789,32.369)
  L4-SIG w0.107: v1(105.789,32.369) 105.66,32.497 105.66,35.829 106.027,36.196 106.027,37.326 106.496,37.795 107.078,37.795 117.158,47.875 117.158,55.867 119.344,58.054 119.344,63.521 120.594,64.771 120.594,66.641 120.122,67.113 120.122,70.821 119.562,71.38 119.562,71.631 v1(119.695,71.764)
PORTB_S9_D5P: J2.14 MC1.109 | length 34.4
  L1-TOP w0.107: MC1.109@106.75,39.59 106.66,39.5 106.66,38.677 v1(106.788,38.549)
  L4-SIG w0.107: v1(106.788,38.549) 106.66,38.677 106.66,39.091 107.378,39.808 108.007,39.808 108.826,40.627 108.826,41.14 115.164,47.477 115.164,55.855 118.151,58.842 118.151,63.363 119.562,64.774 119.562,65.901 v1(119.695,66.034)
PORTB_S10_D4N: J2.15 MC1.104 | length 47.6
  L1-TOP w0.107: v1(105.212,32.369) 105.34,32.497 105.34,33.32 MC1.104@105.25,33.41
  L4-SIG w0.107: v1(105.212,32.369) 105.34,32.497 105.34,35.962 105.707,36.329 105.707,37.459 106.363,38.115 106.945,38.115 116.837,48.007 116.837,56 119.024,58.187 119.024,63.653 120.274,64.903 120.274,66.508 119.802,66.98 119.802,70.688 119.242,71.248 119.242,71.631 v1(119.109,71.764)
PORTB_S11_D5N: J2.16 MC1.107 | length 34.4
  L1-TOP w0.107: v1(106.212,38.549) 106.34,38.677 106.34,39.5 MC1.107@106.25,39.59
  L4-SIG w0.107: v1(106.212,38.549) 106.34,38.677 106.34,39.223 107.245,40.128 107.874,40.128 108.506,40.76 108.506,41.272 114.844,47.61 114.844,55.987 117.831,58.974 117.831,63.495 119.242,64.907 119.242,65.901 v1(119.109,66.034)
PORTB_S12_D6P: J2.17 MC1.101 | length 44
  L1-TOP w0.107: MC1.101@104.75,39.59 104.66,39.5 104.66,38.677 v1(104.789,38.549)
  L4-SIG w0.107: v1(104.789,38.549) 104.66,38.677 104.66,38.894 105.289,39.522 105.971,39.522 106.644,40.196 106.644,42.324 110.655,46.334 110.655,49.104 111.15,49.6 111.15,58.623 117.445,64.917 117.445,66.615 116.972,67.088 116.972,68.248 117.648,68.924 118.227,68.924 118.862,69.558 118.862,70.686 117.962,71.586 117.962,73.833 v1(118.095,73.966)
PORTB_S13_D7P: J2.18 MC1.113 | length 35.3
  L1-TOP w0.107: MC1.113@107.75,39.59 107.66,39.68 107.66,40.504 v1(107.788,40.632)
  L4-SIG w0.107: v1(107.788,40.632) 107.66,40.76 107.66,41.722 111.709,45.771 111.709,47.549 111.872,47.711 113.65,47.711 114.071,48.133 114.071,49.386 113.16,50.298 113.16,59.197 117.04,63.078 117.04,63.363 118.405,64.727 118.405,67.051 117.962,67.494 117.962,68.103 v1(118.095,68.236)
PORTB_S14_D6N: J2.19 MC1.99 | length 44
  L1-TOP w0.107: v1(104.212,38.549) 104.34,38.677 104.34,39.5 MC1.99@104.25,39.59
  L4-SIG w0.107: v1(104.212,38.549) 104.34,38.677 104.34,39.026 105.157,39.842 105.838,39.842 106.324,40.329 106.324,42.456 110.335,46.467 110.335,49.237 110.83,49.732 110.83,58.756 117.125,65.05 117.125,66.483 116.652,66.955 116.652,68.38 117.515,69.244 118.095,69.244 118.542,69.691 118.542,70.554 117.642,71.454 117.642,73.833 v1(117.509,73.966)
PORTB_S15_D7N: J2.20 MC1.111 | length 35.3
  L1-TOP w0.107: v1(107.212,40.632) 107.34,40.504 107.34,39.68 MC1.111@107.25,39.59
  L4-SIG w0.107: v1(107.212,40.632) 107.34,40.76 107.34,41.855 111.389,45.903 111.389,47.681 111.739,48.031 113.517,48.031 113.751,48.266 113.751,49.253 112.84,50.165 112.84,59.33 116.72,63.21 116.72,63.495 118.085,64.86 118.085,66.919 117.642,67.361 117.642,68.103 v1(117.509,68.236)
PORTB_S16: J2.21 MC1.103 | length 37.5
  L1-TOP w0.114: v1(105.212,40.632) 105.34,40.504 105.34,39.68 MC1.103@105.25,39.59
  L4-SIG w0.117: v1(105.212,40.632) 105.212,45.725 108.864,49.378 108.864,58.355 115.918,65.409 115.918,66.288 116.261,66.63 116.261,68.535 117.272,69.546 117.272,71.094 v1(116.602,71.764)
PORTB_S17: J2.22 MC1.105 | length 35.4
  L1-TOP w0.114: MC1.105@105.75,39.59 105.66,39.68 105.66,40.504 v1(105.788,40.632)
  L4-SIG w0.117: v1(105.788,40.632) 105.788,43.965 105.981,44.158 106.194,44.371 106.194,44.477 105.762,44.909 105.762,45.016 106.187,45.441 106.293,45.441 106.779,44.955 107.265,44.47 107.371,44.47 107.796,44.895 107.796,45.001 107.311,45.487 106.825,45.973 106.825,46.079 107.25,46.504 107.357,46.504 107.789,46.072 107.895,46.072 108.134,46.311 108.261,46.438 108.261,47.771 109.131,48.641 109.131,57.734 115.005,63.608 115.232,63.608 116.602,64.977 v1(116.602,66.034)
PORTB_S18: J2.23 MC1.93 | length 42
  L1-TOP w0.114: v1(102.75,38.551) MC1.93@102.75,39.59 ; v1(115.486,70.692) 115.802,71.007 J2.23@115.802,72.865
  L4-SIG w0.117: v1(102.75,38.551) 102.75,49.893 103.06,50.203 103.06,55.728 103.962,56.629 103.962,58.903 109.614,64.554 111.403,64.554 111.901,65.052 112.296,65.052 112.56,65.316 112.56,65.851 114.75,68.04 114.75,69.475 115.486,70.212 v1(115.486,70.692)
PORTB_S19: J2.24 MC1.102 | length 40.3
  L1-TOP w0.114: MC1.102@104.75,33.41 104.66,33.5 104.66,34.324 v1(104.789,34.452)
  L4-SIG w0.117: v1(104.789,34.452) 104.789,35.572 104.597,35.763 104.597,37.059 103.788,37.867 103.788,39.247 104.615,40.074 104.615,46.513 107.163,49.06 107.163,55.791 108.045,56.674 108.045,58.223 115.486,65.664 115.486,66.681 115.802,66.997 v1(115.802,68.236)
PORTB_S20: J2.25 MC1.94 | length 56.1
  L1-TOP w0.114: MC1.94@102.75,33.41 v1(102.75,34.45)
  L4-SIG w0.117: v1(102.75,34.45) 102.921,34.621 102.921,35.027 102.21,35.738 101.016,35.738 100.228,36.525 100.228,37.059 99.238,38.049 99.238,38.608 97.384,40.462 97.384,45.757 93.122,50.019 93.122,55.861 100.907,63.646 101.58,63.646 106.692,68.758 112.61,68.758 115.001,71.149 v1(115.001,71.764)
PORTB_S21: J2.26 MC1.100 | length 37.9
  L1-TOP w0.114: v1(104.212,34.452) 104.34,34.324 104.34,33.5 MC1.100@104.25,33.41
  L4-SIG w0.117: v1(104.212,34.452) 104.212,37.012 103.403,37.821 103.403,39.395 104.242,40.234 104.242,46.736 106.87,49.365 106.87,56.382 107.163,56.674 107.163,58.094 115.001,65.933 v1(115.001,66.034)
PORTB_S22: J2.27 MC1.92 | length 56.7
  L1-TOP w0.114: MC1.92@102.25,33.41 102.25,34.724 v1(102.433,34.907) ; v1(114.201,71.399) J2.27@114.201,72.865
  L4-SIG w0.117: v1(102.433,34.907) 101.059,34.907 98.397,37.57 98.397,38.535 96.088,40.843 96.088,45.39 92.842,48.636 92.842,56.14 100.818,64.116 101.327,64.116 106.35,69.139 111.553,69.139 113.146,70.733 113.534,70.733 v1(114.201,71.399)
PORTB_S23: J2.28 MC1.98 | length 50.2
  L1-TOP w0.114: v1(103.75,32.371) MC1.98@103.75,33.41
  L4-SIG w0.117: v1(103.75,32.371) 103.75,35.137 101.829,37.059 101.829,38.397 100.279,39.946 100.279,45.822 96.965,49.136 96.965,56.642 104.654,64.332 105.72,64.332 108.069,66.681 110.94,66.681 111.498,67.24 113.205,67.24 v1(114.201,68.236)
PORTB_S24: J2.29 MC1.90 | length 58.3
  L1-TOP w0.114: v1(101.75,32.371) MC1.90@101.75,33.41
  L4-SIG w0.117: v1(101.75,32.371) 101.75,33.657 99.949,35.458 99.06,35.458 98.336,36.182 98.336,36.9 97.511,37.726 97.511,38.32 94.64,41.191 94.64,44.501 91.961,47.18 91.961,48.857 91.013,49.804 91.013,55.569 100.018,64.573 101.073,64.573 106.05,69.55 110.595,69.55 111.448,70.402 112.04,70.402 v1(113.401,71.764)
PORTB_S25: J2.30 MC1.91 | length 38.4
  L1-TOP w0.114: MC1.91@102.25,39.59 102.25,38.276 v1(102.433,38.094) ; v1(112.057,65.53) 112.837,65.53 113.255,65.948 113.255,66.989 J2.30@113.401,67.135
  L4-SIG w0.117: v1(102.433,38.094) 102.159,38.368 102.159,39.7 102.337,39.878 102.337,47.422 101.054,48.704 101.054,56.972 106.952,62.87 106.952,62.973 108.87,64.891 111.375,64.891 112.014,65.53 v1(112.057,65.53)
PORTB_S26: J2.31 MC1.88 | length 59.4
  L1-TOP w0.114: MC1.88@101.25,33.41 101.25,32.096 v1(101.433,31.913)
  L4-SIG w0.117: v1(101.433,31.913) 98.982,34.365 98.982,34.901 98,35.883 98,36.626 93.04,41.586 93.04,44.704 90.683,47.061 90.683,55.927 100.618,65.862 101.575,65.862 106.343,70.631 109.266,70.631 v1(112.601,73.966)
PORTB_S27: J2.32 MC1.96 | length 52.1
  L1-TOP w0.114: MC1.96@103.25,33.41 103.25,32.096 v1(103.433,31.913)
  L4-SIG w0.117: v1(103.433,31.913) 103.149,32.197 103.149,33.274 103.276,33.401 103.276,35.027 101.498,36.805 101.498,38.1 99.695,39.903 99.695,44.691 95.034,49.352 95.034,55.956 103.536,64.458 103.536,64.852 104.615,65.932 106.736,65.932 108.425,67.621 110.648,67.621 111.263,68.236 v1(112.601,68.236)
PORTC_C2P_CLKN: J4.36 MC2.58 | length 55.9
  L1-TOP w0.107: J4.36@53.001,-67.135 52.906,-67.228 52.906,-68.38 53.359,-68.833 53.359,-69.079 53.492,-69.212 v1(53.492,-69.291) ; MC2.58@88.75,-39.59 88.66,-39.68 88.66,-40.503 v1(88.788,-40.631)
  L4-SIG w0.107: v1(53.492,-69.291) 53.492,-69.212 53.359,-69.079 53.359,-68.986 53.512,-68.834 57.247,-68.834 60.069,-66.012 60.353,-66.012 61.758,-64.607 72.929,-64.607 82.819,-54.717 82.819,-51.191 86.756,-47.254 86.756,-43.389 88.66,-41.485 88.66,-40.759 v1(88.788,-40.631)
